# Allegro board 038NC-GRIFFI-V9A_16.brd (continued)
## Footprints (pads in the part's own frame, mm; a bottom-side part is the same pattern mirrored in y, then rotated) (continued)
PG_LTXDX_F_X1_PG400ND_SL12_V3
  round 0.051 hole 2.489x2.21 unplated: (36.185,-220.342)
  round 0.508 hole 3.2 unplated: (37.185,-154.842)
  rect 1.016x1.016 smd: A1(41.814,-218.796)
  round 1.016 smd: A2(42.939,-217.796) A3(41.814,-216.796) A4(42.939,-215.796) B1(39.565,-218.796) B2(40.69,-217.796) B3(39.565,-216.796) B4(40.69,-215.796) B62(40.69,-157.796) C1(37.314,-218.796) C2(38.44,-217.796) C3(37.314,-216.796) C4(38.44,-215.796) C62(38.44,-157.796) D1(35.064,-218.796) D2(36.189,-217.796) D3(35.064,-216.796) D4(36.189,-215.796) E1(32.815,-218.796) E2(33.939,-217.796) E3(32.815,-216.796) E4(33.939,-215.796) E62(33.939,-157.796) F1(30.565,-218.796) F2(31.69,-217.796) F3(30.565,-216.796) F4(31.69,-215.796) F62(31.69,-157.796) G2(29.44,-217.796) G4(29.44,-215.796) G6(29.44,-213.796) G8(29.44,-211.796) G10(29.44,-209.796) G12(29.44,-207.796) G14(29.44,-205.796) G16(29.44,-203.796) G18(29.44,-201.796) G20(29.44,-199.796) G22(29.44,-197.796) G24(29.44,-195.796) G26(29.44,-193.796) G28(29.44,-191.796) G30(29.44,-189.796) G32(29.44,-187.796) G34(29.44,-185.796) G36(29.44,-183.796) G38(29.44,-181.796) G40(29.44,-179.796) G42(29.44,-177.796) G44(29.44,-175.796) G46(29.44,-173.796) G48(29.44,-171.796) G50(29.44,-169.796) G52(29.44,-167.796) G54(29.44,-165.796) G56(29.44,-163.796) G58(29.44,-161.796) G60(29.44,-159.796)
  custom 0.257x0.257 smd: A5(41.814,-214.796) A6(42.939,-213.796) A7(41.814,-212.796) A8(42.939,-211.796) A9(41.814,-210.796) A10(42.939,-209.796) A11(41.814,-208.796) A12(42.939,-207.796) A13(41.814,-206.796) A14(42.939,-205.796) A15(41.814,-204.796) A16(42.939,-203.796) A17(41.814,-202.796) A18(42.939,-201.796) A19(41.814,-200.796) A20(42.939,-199.796) A21(41.814,-198.796) A22(42.939,-197.796) A23(41.814,-196.796) A24(42.939,-195.796) A25(41.814,-194.796) A26(42.939,-193.796) A27(41.814,-192.796) A28(42.939,-191.796) A29(41.814,-190.796) A30(42.939,-189.796) A31(41.814,-188.796) A32(42.939,-187.796) A33(41.814,-186.796) A34(42.939,-185.796) A35(41.814,-184.796) A36(42.939,-183.796) A37(41.814,-182.796) A38(42.939,-181.796) A39(41.814,-180.796) A40(42.939,-179.796) A41(41.814,-178.796) A42(42.939,-177.796) A43(41.814,-176.796) A44(42.939,-175.796) A45(41.814,-174.796) A46(42.939,-173.796) A47(41.814,-172.796) A48(42.939,-171.796) A49(41.814,-170.796) A50(42.939,-169.796) A51(41.814,-168.796) A52(42.939,-167.796) A53(41.814,-166.796) A54(42.939,-165.796) A55(41.814,-164.796) A56(42.939,-163.796) A57(41.814,-162.796) A58(42.939,-161.796) A59(41.814,-160.796) A60(42.939,-159.796) A61(41.814,-158.796) B5(39.565,-214.796) B6(40.69,-213.796) B7(39.565,-212.796) B8(40.69,-211.796) B9(39.565,-210.796) B10(40.69,-209.796) B11(39.565,-208.796) B12(40.69,-207.796) B13(39.565,-206.796) B14(40.69,-205.796) B15(39.565,-204.796) B16(40.69,-203.796) B17(39.565,-202.796) B18(40.69,-201.796) B19(39.565,-200.796) B20(40.69,-199.796) B21(39.565,-198.796) B22(40.69,-197.796) B23(39.565,-196.796) B24(40.69,-195.796) B25(39.565,-194.796) B26(40.69,-193.796) B27(39.565,-192.796) B28(40.69,-191.796) B29(39.565,-190.796) B30(40.69,-189.796) B31(39.565,-188.796) B32(40.69,-187.796) B33(39.565,-186.796) B34(40.69,-185.796) B35(39.565,-184.796) B36(40.69,-183.796) B37(39.565,-182.796) B38(40.69,-181.796) B39(39.565,-180.796) B40(40.69,-179.796) B41(39.565,-178.796) B42(40.69,-177.796) B43(39.565,-176.796) B44(40.69,-175.796) B45(39.565,-174.796) B46(40.69,-173.796) B47(39.565,-172.796) B48(40.69,-171.796) B49(39.565,-170.796) B50(40.69,-169.796) B51(39.565,-168.796) B52(40.69,-167.796) B53(39.565,-166.796) B54(40.69,-165.796) B55(39.565,-164.796) B56(40.69,-163.796) B57(39.565,-162.796) B58(40.69,-161.796) B59(39.565,-160.796) B60(40.69,-159.796) B61(39.565,-158.796) C5(37.314,-214.796) C6(38.44,-213.796) C7(37.314,-212.796) C8(38.44,-211.796) C9(37.314,-210.796) C10(38.44,-209.796) C11(37.314,-208.796) C12(38.44,-207.796) C13(37.314,-206.796) C14(38.44,-205.796) C15(37.314,-204.796) C16(38.44,-203.796) C17(37.314,-202.796) C18(38.44,-201.796) C19(37.314,-200.796) C20(38.44,-199.796) C21(37.314,-198.796) C22(38.44,-197.796) C23(37.314,-196.796) C24(38.44,-195.796) C25(37.314,-194.796) C26(38.44,-193.796) C27(37.314,-192.796) C28(38.44,-191.796) C29(37.314,-190.796) C30(38.44,-189.796) C31(37.314,-188.796) C32(38.44,-187.796) C33(37.314,-186.796) C34(38.44,-185.796) C35(37.314,-184.796) C36(38.44,-183.796) C37(37.314,-182.796) C38(38.44,-181.796) C39(37.314,-180.796) C40(38.44,-179.796) C41(37.314,-178.796) C42(38.44,-177.796) C43(37.314,-176.796) C44(38.44,-175.796) C45(37.314,-174.796) C46(38.44,-173.796) C47(37.314,-172.796) C48(38.44,-171.796) C49(37.314,-170.796) C50(38.44,-169.796) C51(37.314,-168.796) C52(38.44,-167.796) C53(37.314,-166.796) C54(38.44,-165.796) C55(37.314,-164.796) C56(38.44,-163.796) C57(37.314,-162.796) C58(38.44,-161.796) C59(37.314,-160.796) C60(38.44,-159.796) C61(37.314,-158.796) D5(35.064,-214.796) D6(36.189,-213.796) D7(35.064,-212.796) D8(36.189,-211.796) D9(35.064,-210.796) D10(36.189,-209.796) D11(35.064,-208.796) D12(36.189,-207.796) D13(35.064,-206.796) D14(36.189,-205.796) D15(35.064,-204.796) D16(36.189,-203.796) D17(35.064,-202.796) D18(36.189,-201.796) D19(35.064,-200.796) D20(36.189,-199.796) D21(35.064,-198.796) D22(36.189,-197.796) D23(35.064,-196.796) D24(36.189,-195.796) D25(35.064,-194.796) D26(36.189,-193.796) D27(35.064,-192.796) D28(36.189,-191.796) D29(35.064,-190.796) D30(36.189,-189.796) D31(35.064,-188.796) D32(36.189,-187.796) D33(35.064,-186.796) D34(36.189,-185.796) D35(35.064,-184.796) D36(36.189,-183.796) D37(35.064,-182.796) D38(36.189,-181.796) D39(35.064,-180.796) D40(36.189,-179.796) D41(35.064,-178.796) D42(36.189,-177.796) D43(35.064,-176.796) D44(36.189,-175.796) D45(35.064,-174.796) D46(36.189,-173.796) D47(35.064,-172.796) D48(36.189,-171.796) D49(35.064,-170.796) D50(36.189,-169.796) D51(35.064,-168.796) D52(36.189,-167.796) D53(35.064,-166.796) D54(36.189,-165.796) D55(35.064,-164.796) D56(36.189,-163.796) D57(35.064,-162.796) D58(36.189,-161.796) D59(35.064,-160.796) D60(36.189,-159.796) D61(35.064,-158.796) E5(32.815,-214.796) E6(33.939,-213.796) E7(32.815,-212.796) E8(33.939,-211.796) E9(32.815,-210.796) E10(33.939,-209.796) E11(32.815,-208.796) E12(33.939,-207.796) E13(32.815,-206.796) E14(33.939,-205.796) E15(32.815,-204.796) E16(33.939,-203.796) E17(32.815,-202.796) E18(33.939,-201.796) E19(32.815,-200.796) E20(33.939,-199.796) E21(32.815,-198.796) E22(33.939,-197.796) E23(32.815,-196.796) E24(33.939,-195.796) E25(32.815,-194.796) E26(33.939,-193.796) E27(32.815,-192.796) E28(33.939,-191.796) E29(32.815,-190.796) E30(33.939,-189.796) E31(32.815,-188.796) E32(33.939,-187.796) E33(32.815,-186.796) E34(33.939,-185.796) E35(32.815,-184.796) E36(33.939,-183.796) E37(32.815,-182.796) E38(33.939,-181.796) E39(32.815,-180.796) E40(33.939,-179.796) E41(32.815,-178.796) E42(33.939,-177.796) E43(32.815,-176.796) E44(33.939,-175.796) E45(32.815,-174.796) E46(33.939,-173.796) E47(32.815,-172.796) E48(33.939,-171.796) E49(32.815,-170.796) E50(33.939,-169.796) E51(32.815,-168.796) E52(33.939,-167.796) E53(32.815,-166.796) E54(33.939,-165.796) E55(32.815,-164.796) E56(33.939,-163.796) E57(32.815,-162.796) E58(33.939,-161.796) E59(32.815,-160.796) E60(33.939,-159.796) E61(32.815,-158.796) F5(30.565,-214.796) F6(31.69,-213.796) F7(30.565,-212.796) F8(31.69,-211.796) F9(30.565,-210.796) F10(31.69,-209.796) F11(30.565,-208.796) F12(31.69,-207.796) F13(30.565,-206.796) F14(31.69,-205.796) F15(30.565,-204.796) F16(31.69,-203.796) F17(30.565,-202.796) F18(31.69,-201.796) F19(30.565,-200.796) F20(31.69,-199.796) F21(30.565,-198.796) F22(31.69,-197.796) F23(30.565,-196.796) F24(31.69,-195.796) F25(30.565,-194.796) F26(31.69,-193.796) F27(30.565,-192.796) F28(31.69,-191.796) F29(30.565,-190.796) F30(31.69,-189.796) F31(30.565,-188.796) F32(31.69,-187.796) F33(30.565,-186.796) F34(31.69,-185.796) F35(30.565,-184.796) F36(31.69,-183.796) F37(30.565,-182.796) F38(31.69,-181.796) F39(30.565,-180.796) F40(31.69,-179.796) F41(30.565,-178.796) F42(31.69,-177.796) F43(30.565,-176.796) F44(31.69,-175.796) F45(30.565,-174.796) F46(31.69,-173.796) F47(30.565,-172.796) F48(31.69,-171.796) F49(30.565,-170.796) F50(31.69,-169.796) F51(30.565,-168.796) F52(31.69,-167.796) F53(30.565,-166.796) F54(31.69,-165.796) F55(30.565,-164.796) F56(31.69,-163.796) F57(30.565,-162.796) F58(31.69,-161.796) F59(30.565,-160.796) F60(31.69,-159.796) F61(30.565,-158.796) Z5(44.064,-214.796) Z7(44.064,-212.796) Z9(44.064,-210.796) Z11(44.064,-208.796) Z13(44.064,-206.796) Z15(44.064,-204.796) Z17(44.064,-202.796) Z19(44.064,-200.796) Z21(44.064,-198.796) Z23(44.064,-196.796) Z25(44.064,-194.796) Z27(44.064,-192.796) Z29(44.064,-190.796) Z31(44.064,-188.796) Z33(44.064,-186.796) Z35(44.064,-184.796) Z37(44.064,-182.796) Z39(44.064,-180.796) Z41(44.064,-178.796) Z43(44.064,-176.796) Z45(44.064,-174.796) Z47(44.064,-172.796) Z49(44.064,-170.796) Z51(44.064,-168.796) Z53(44.064,-166.796) Z55(44.064,-164.796) Z57(44.064,-162.796) Z59(44.064,-160.796) Z61(44.064,-158.796)
PG_LTXDX_F_X1_PG400ND_SL14_V3
  round 0.051 hole 2.489x2.21 unplated: (60.315,-220.342)
  round 0.508 hole 3.2 unplated: (61.315,-154.842)
  rect 1.016x1.016 smd: A1(65.944,-218.796)
  round 1.016 smd: A2(67.069,-217.796) A3(65.944,-216.796) A4(67.069,-215.796) B1(63.695,-218.796) B2(64.82,-217.796) B3(63.695,-216.796) B4(64.82,-215.796) B62(64.82,-157.796) C1(61.444,-218.796) C2(62.57,-217.796) C3(61.444,-216.796) C4(62.57,-215.796) C62(62.57,-157.796) D1(59.194,-218.796) D2(60.319,-217.796) D3(59.194,-216.796) D4(60.319,-215.796) E1(56.945,-218.796) E2(58.069,-217.796) E3(56.945,-216.796) E4(58.069,-215.796) E62(58.069,-157.796) F1(54.695,-218.796) F2(55.82,-217.796) F3(54.695,-216.796) F4(55.82,-215.796) F62(55.82,-157.796) G2(53.57,-217.796) G4(53.57,-215.796) G6(53.57,-213.796) G8(53.57,-211.796) G10(53.57,-209.796) G12(53.57,-207.796) G14(53.57,-205.796) G16(53.57,-203.796) G18(53.57,-201.796) G20(53.57,-199.796) G22(53.57,-197.796) G24(53.57,-195.796) G26(53.57,-193.796) G28(53.57,-191.796) G30(53.57,-189.796) G32(53.57,-187.796) G34(53.57,-185.796) G36(53.57,-183.796) G38(53.57,-181.796) G40(53.57,-179.796) G42(53.57,-177.796) G44(53.57,-175.796) G46(53.57,-173.796) G48(53.57,-171.796) G50(53.57,-169.796) G52(53.57,-167.796) G54(53.57,-165.796) G56(53.57,-163.796) G58(53.57,-161.796) G60(53.57,-159.796)
  custom 0.257x0.257 smd: A5(65.944,-214.796) A6(67.069,-213.796) A7(65.944,-212.796) A8(67.069,-211.796) A9(65.944,-210.796) A10(67.069,-209.796) A11(65.944,-208.796) A12(67.069,-207.796) A13(65.944,-206.796) A14(67.069,-205.796) A15(65.944,-204.796) A16(67.069,-203.796) A17(65.944,-202.796) A18(67.069,-201.796) A19(65.944,-200.796) A20(67.069,-199.796) A21(65.944,-198.796) A22(67.069,-197.796) A23(65.944,-196.796) A24(67.069,-195.796) A25(65.944,-194.796) A26(67.069,-193.796) A27(65.944,-192.796) A28(67.069,-191.796) A29(65.944,-190.796) A30(67.069,-189.796) A31(65.944,-188.796) A32(67.069,-187.796) A33(65.944,-186.796) A34(67.069,-185.796) A35(65.944,-184.796) A36(67.069,-183.796) A37(65.944,-182.796) A38(67.069,-181.796) A39(65.944,-180.796) A40(67.069,-179.796) A41(65.944,-178.796) A42(67.069,-177.796) A43(65.944,-176.796) A44(67.069,-175.796) A45(65.944,-174.796) A46(67.069,-173.796) A47(65.944,-172.796) A48(67.069,-171.796) A49(65.944,-170.796) A50(67.069,-169.796) A51(65.944,-168.796) A52(67.069,-167.796) A53(65.944,-166.796) A54(67.069,-165.796) A55(65.944,-164.796) A56(67.069,-163.796) A57(65.944,-162.796) A58(67.069,-161.796) A59(65.944,-160.796) A60(67.069,-159.796) A61(65.944,-158.796) B5(63.695,-214.796) B6(64.82,-213.796) B7(63.695,-212.796) B8(64.82,-211.796) B9(63.695,-210.796) B10(64.82,-209.796) B11(63.695,-208.796) B12(64.82,-207.796) B13(63.695,-206.796) B14(64.82,-205.796) B15(63.695,-204.796) B16(64.82,-203.796) B17(63.695,-202.796) B18(64.82,-201.796) B19(63.695,-200.796) B20(64.82,-199.796) B21(63.695,-198.796) B22(64.82,-197.796) B23(63.695,-196.796) B24(64.82,-195.796) B25(63.695,-194.796) B26(64.82,-193.796) B27(63.695,-192.796) B28(64.82,-191.796) B29(63.695,-190.796) B30(64.82,-189.796) B31(63.695,-188.796) B32(64.82,-187.796) B33(63.695,-186.796) B34(64.82,-185.796) B35(63.695,-184.796) B36(64.82,-183.796) B37(63.695,-182.796) B38(64.82,-181.796) B39(63.695,-180.796) B40(64.82,-179.796) B41(63.695,-178.796) B42(64.82,-177.796) B43(63.695,-176.796) B44(64.82,-175.796) B45(63.695,-174.796) B46(64.82,-173.796) B47(63.695,-172.796) B48(64.82,-171.796) B49(63.695,-170.796) B50(64.82,-169.796) B51(63.695,-168.796) B52(64.82,-167.796) B53(63.695,-166.796) B54(64.82,-165.796) B55(63.695,-164.796) B56(64.82,-163.796) B57(63.695,-162.796) B58(64.82,-161.796) B59(63.695,-160.796) B60(64.82,-159.796) B61(63.695,-158.796) C5(61.444,-214.796) C6(62.57,-213.796) C7(61.444,-212.796) C8(62.57,-211.796) C9(61.444,-210.796) C10(62.57,-209.796) C11(61.444,-208.796) C12(62.57,-207.796) C13(61.444,-206.796) C14(62.57,-205.796) C15(61.444,-204.796) C16(62.57,-203.796) C17(61.444,-202.796) C18(62.57,-201.796) C19(61.444,-200.796) C20(62.57,-199.796) C21(61.444,-198.796) C22(62.57,-197.796) C23(61.444,-196.796) C24(62.57,-195.796) C25(61.444,-194.796) C26(62.57,-193.796) C27(61.444,-192.796) C28(62.57,-191.796) C29(61.444,-190.796) C30(62.57,-189.796) C31(61.444,-188.796) C32(62.57,-187.796) C33(61.444,-186.796) C34(62.57,-185.796) C35(61.444,-184.796) C36(62.57,-183.796) C37(61.444,-182.796) C38(62.57,-181.796) C39(61.444,-180.796) C40(62.57,-179.796) C41(61.444,-178.796) C42(62.57,-177.796) C43(61.444,-176.796) C44(62.57,-175.796) C45(61.444,-174.796) C46(62.57,-173.796) C47(61.444,-172.796) C48(62.57,-171.796) C49(61.444,-170.796) C50(62.57,-169.796) C51(61.444,-168.796) C52(62.57,-167.796) C53(61.444,-166.796) C54(62.57,-165.796) C55(61.444,-164.796) C56(62.57,-163.796) C57(61.444,-162.796) C58(62.57,-161.796) C59(61.444,-160.796) C60(62.57,-159.796) C61(61.444,-158.796) D5(59.194,-214.796) D6(60.319,-213.796) D7(59.194,-212.796) D8(60.319,-211.796) D9(59.194,-210.796) D10(60.319,-209.796) D11(59.194,-208.796) D12(60.319,-207.796) D13(59.194,-206.796) D14(60.319,-205.796) D15(59.194,-204.796) D16(60.319,-203.796) D17(59.194,-202.796) D18(60.319,-201.796) D19(59.194,-200.796) D20(60.319,-199.796) D21(59.194,-198.796) D22(60.319,-197.796) D23(59.194,-196.796) D24(60.319,-195.796) D25(59.194,-194.796) D26(60.319,-193.796) D27(59.194,-192.796) D28(60.319,-191.796) D29(59.194,-190.796) D30(60.319,-189.796) D31(59.194,-188.796) D32(60.319,-187.796) D33(59.194,-186.796) D34(60.319,-185.796) D35(59.194,-184.796) D36(60.319,-183.796) D37(59.194,-182.796) D38(60.319,-181.796) D39(59.194,-180.796) D40(60.319,-179.796) D41(59.194,-178.796) D42(60.319,-177.796) D43(59.194,-176.796) D44(60.319,-175.796) D45(59.194,-174.796) D46(60.319,-173.796) D47(59.194,-172.796) D48(60.319,-171.796) D49(59.194,-170.796) D50(60.319,-169.796) D51(59.194,-168.796) D52(60.319,-167.796) D53(59.194,-166.796) D54(60.319,-165.796) D55(59.194,-164.796) D56(60.319,-163.796) D57(59.194,-162.796) D58(60.319,-161.796) D59(59.194,-160.796) D60(60.319,-159.796) D61(59.194,-158.796) E5(56.945,-214.796) E6(58.069,-213.796) E7(56.945,-212.796) E8(58.069,-211.796) E9(56.945,-210.796) E10(58.069,-209.796) E11(56.945,-208.796) E12(58.069,-207.796) E13(56.945,-206.796) E14(58.069,-205.796) E15(56.945,-204.796) E16(58.069,-203.796) E17(56.945,-202.796) E18(58.069,-201.796) E19(56.945,-200.796) E20(58.069,-199.796) E21(56.945,-198.796) E22(58.069,-197.796) E23(56.945,-196.796) E24(58.069,-195.796) E25(56.945,-194.796) E26(58.069,-193.796) E27(56.945,-192.796) E28(58.069,-191.796) E29(56.945,-190.796) E30(58.069,-189.796) E31(56.945,-188.796) E32(58.069,-187.796) E33(56.945,-186.796) E34(58.069,-185.796) E35(56.945,-184.796) E36(58.069,-183.796) E37(56.945,-182.796) E38(58.069,-181.796) E39(56.945,-180.796) E40(58.069,-179.796) E41(56.945,-178.796) E42(58.069,-177.796) E43(56.945,-176.796) E44(58.069,-175.796) E45(56.945,-174.796) E46(58.069,-173.796) E47(56.945,-172.796) E48(58.069,-171.796) E49(56.945,-170.796) E50(58.069,-169.796) E51(56.945,-168.796) E52(58.069,-167.796) E53(56.945,-166.796) E54(58.069,-165.796) E55(56.945,-164.796) E56(58.069,-163.796) E57(56.945,-162.796) E58(58.069,-161.796) E59(56.945,-160.796) E60(58.069,-159.796) E61(56.945,-158.796) F5(54.695,-214.796) F6(55.82,-213.796) F7(54.695,-212.796) F8(55.82,-211.796) F9(54.695,-210.796) F10(55.82,-209.796) F11(54.695,-208.796) F12(55.82,-207.796) F13(54.695,-206.796) F14(55.82,-205.796) F15(54.695,-204.796) F16(55.82,-203.796) F17(54.695,-202.796) F18(55.82,-201.796) F19(54.695,-200.796) F20(55.82,-199.796) F21(54.695,-198.796) F22(55.82,-197.796) F23(54.695,-196.796) F24(55.82,-195.796) F25(54.695,-194.796) F26(55.82,-193.796) F27(54.695,-192.796) F28(55.82,-191.796) F29(54.695,-190.796) F30(55.82,-189.796) F31(54.695,-188.796) F32(55.82,-187.796) F33(54.695,-186.796) F34(55.82,-185.796) F35(54.695,-184.796) F36(55.82,-183.796) F37(54.695,-182.796) F38(55.82,-181.796) F39(54.695,-180.796) F40(55.82,-179.796) F41(54.695,-178.796) F42(55.82,-177.796) F43(54.695,-176.796) F44(55.82,-175.796) F45(54.695,-174.796) F46(55.82,-173.796) F47(54.695,-172.796) F48(55.82,-171.796) F49(54.695,-170.796) F50(55.82,-169.796) F51(54.695,-168.796) F52(55.82,-167.796) F53(54.695,-166.796) F54(55.82,-165.796) F55(54.695,-164.796) F56(55.82,-163.796) F57(54.695,-162.796) F58(55.82,-161.796) F59(54.695,-160.796) F60(55.82,-159.796) F61(54.695,-158.796) Z5(68.194,-214.796) Z7(68.194,-212.796) Z9(68.194,-210.796) Z11(68.194,-208.796) Z13(68.194,-206.796) Z15(68.194,-204.796) Z17(68.194,-202.796) Z19(68.194,-200.796) Z21(68.194,-198.796) Z23(68.194,-196.796) Z25(68.194,-194.796) Z27(68.194,-192.796) Z29(68.194,-190.796) Z31(68.194,-188.796) Z33(68.194,-186.796) Z35(68.194,-184.796) Z37(68.194,-182.796) Z39(68.194,-180.796) Z41(68.194,-178.796) Z43(68.194,-176.796) Z45(68.194,-174.796) Z47(68.194,-172.796) Z49(68.194,-170.796) Z51(68.194,-168.796) Z53(68.194,-166.796) Z55(68.194,-164.796) Z57(68.194,-162.796) Z59(68.194,-160.796) Z61(68.194,-158.796)
PG_LTXDX_F_X1_PG400ND_SL15_V3
  round 0.508 hole 3.2 unplated: (59.335,154.842)
  round 0.051 hole 2.489x2.21 unplated: (60.335,220.342)
  rect 1.016x1.016 smd: A1(54.706,218.796)
  round 1.016 smd: A2(53.581,217.796) A3(54.706,216.796) A4(53.581,215.796) B1(56.955,218.796) B2(55.83,217.796) B3(56.955,216.796) B4(55.83,215.796) B62(55.83,157.796) C1(59.206,218.796) C2(58.08,217.796) C3(59.206,216.796) C4(58.08,215.796) C62(58.08,157.796) D1(61.456,218.796) D2(60.331,217.796) D3(61.456,216.796) D4(60.331,215.796) E1(63.705,218.796) E2(62.581,217.796) E3(63.705,216.796) E4(62.581,215.796) E62(62.581,157.796) F1(65.955,218.796) F2(64.83,217.796) F3(65.955,216.796) F4(64.83,215.796) F62(64.83,157.796) G2(67.08,217.796) G4(67.08,215.796) G6(67.08,213.796) G8(67.08,211.796) G10(67.08,209.796) G12(67.08,207.796) G14(67.08,205.796) G16(67.08,203.796) G18(67.08,201.796) G20(67.08,199.796) G22(67.08,197.796) G24(67.08,195.796) G26(67.08,193.796) G28(67.08,191.796) G30(67.08,189.796) G32(67.08,187.796) G34(67.08,185.796) G36(67.08,183.796) G38(67.08,181.796) G40(67.08,179.796) G42(67.08,177.796) G44(67.08,175.796) G46(67.08,173.796) G48(67.08,171.796) G50(67.08,169.796) G52(67.08,167.796) G54(67.08,165.796) G56(67.08,163.796) G58(67.08,161.796) G60(67.08,159.796)
  custom 0.257x0.257 smd: A5(54.706,214.796) A6(53.581,213.796) A7(54.706,212.796) A8(53.581,211.796) A9(54.706,210.796) A10(53.581,209.796) A11(54.706,208.796) A12(53.581,207.796) A13(54.706,206.796) A14(53.581,205.796) A15(54.706,204.796) A16(53.581,203.796) A17(54.706,202.796) A18(53.581,201.796) A19(54.706,200.796) A20(53.581,199.796) A21(54.706,198.796) A22(53.581,197.796) A23(54.706,196.796) A24(53.581,195.796) A25(54.706,194.796) A26(53.581,193.796) A27(54.706,192.796) A28(53.581,191.796) A29(54.706,190.796) A30(53.581,189.796) A31(54.706,188.796) A32(53.581,187.796) A33(54.706,186.796) A34(53.581,185.796) A35(54.706,184.796) A36(53.581,183.796) A37(54.706,182.796) A38(53.581,181.796) A39(54.706,180.796) A40(53.581,179.796) A41(54.706,178.796) A42(53.581,177.796) A43(54.706,176.796) A44(53.581,175.796) A45(54.706,174.796) A46(53.581,173.796) A47(54.706,172.796) A48(53.581,171.796) A49(54.706,170.796) A50(53.581,169.796) A51(54.706,168.796) A52(53.581,167.796) A53(54.706,166.796) A54(53.581,165.796) A55(54.706,164.796) A56(53.581,163.796) A57(54.706,162.796) A58(53.581,161.796) A59(54.706,160.796) A60(53.581,159.796) A61(54.706,158.796) B5(56.955,214.796) B6(55.83,213.796) B7(56.955,212.796) B8(55.83,211.796) B9(56.955,210.796) B10(55.83,209.796) B11(56.955,208.796) B12(55.83,207.796) B13(56.955,206.796) B14(55.83,205.796) B15(56.955,204.796) B16(55.83,203.796) B17(56.955,202.796) B18(55.83,201.796) B19(56.955,200.796) B20(55.83,199.796) B21(56.955,198.796) B22(55.83,197.796) B23(56.955,196.796) B24(55.83,195.796) B25(56.955,194.796) B26(55.83,193.796) B27(56.955,192.796) B28(55.83,191.796) B29(56.955,190.796) B30(55.83,189.796) B31(56.955,188.796) B32(55.83,187.796) B33(56.955,186.796) B34(55.83,185.796) B35(56.955,184.796) B36(55.83,183.796) B37(56.955,182.796) B38(55.83,181.796) B39(56.955,180.796) B40(55.83,179.796) B41(56.955,178.796) B42(55.83,177.796) B43(56.955,176.796) B44(55.83,175.796) B45(56.955,174.796) B46(55.83,173.796) B47(56.955,172.796) B48(55.83,171.796) B49(56.955,170.796) B50(55.83,169.796) B51(56.955,168.796) B52(55.83,167.796) B53(56.955,166.796) B54(55.83,165.796) B55(56.955,164.796) B56(55.83,163.796) B57(56.955,162.796) B58(55.83,161.796) B59(56.955,160.796) B60(55.83,159.796) B61(56.955,158.796) C5(59.206,214.796) C6(58.08,213.796) C7(59.206,212.796) C8(58.08,211.796) C9(59.206,210.796) C10(58.08,209.796) C11(59.206,208.796) C12(58.08,207.796) C13(59.206,206.796) C14(58.08,205.796) C15(59.206,204.796) C16(58.08,203.796) C17(59.206,202.796) C18(58.08,201.796) C19(59.206,200.796) C20(58.08,199.796) C21(59.206,198.796) C22(58.08,197.796) C23(59.206,196.796) C24(58.08,195.796) C25(59.206,194.796) C26(58.08,193.796) C27(59.206,192.796) C28(58.08,191.796) C29(59.206,190.796) C30(58.08,189.796) C31(59.206,188.796) C32(58.08,187.796) C33(59.206,186.796) C34(58.08,185.796) C35(59.206,184.796) C36(58.08,183.796) C37(59.206,182.796) C38(58.08,181.796) C39(59.206,180.796) C40(58.08,179.796) C41(59.206,178.796) C42(58.08,177.796) C43(59.206,176.796) C44(58.08,175.796) C45(59.206,174.796) C46(58.08,173.796) C47(59.206,172.796) C48(58.08,171.796) C49(59.206,170.796) C50(58.08,169.796) C51(59.206,168.796) C52(58.08,167.796) C53(59.206,166.796) C54(58.08,165.796) C55(59.206,164.796) C56(58.08,163.796) C57(59.206,162.796) C58(58.08,161.796) C59(59.206,160.796) C60(58.08,159.796) C61(59.206,158.796) D5(61.456,214.796) D6(60.331,213.796) D7(61.456,212.796) D8(60.331,211.796) D9(61.456,210.796) D10(60.331,209.796) D11(61.456,208.796) D12(60.331,207.796) D13(61.456,206.796) D14(60.331,205.796) D15(61.456,204.796) D16(60.331,203.796) D17(61.456,202.796) D18(60.331,201.796) D19(61.456,200.796) D20(60.331,199.796) D21(61.456,198.796) D22(60.331,197.796) D23(61.456,196.796) D24(60.331,195.796) D25(61.456,194.796) D26(60.331,193.796) D27(61.456,192.796) D28(60.331,191.796) D29(61.456,190.796) D30(60.331,189.796) D31(61.456,188.796) D32(60.331,187.796) D33(61.456,186.796) D34(60.331,185.796) D35(61.456,184.796) D36(60.331,183.796) D37(61.456,182.796) D38(60.331,181.796) D39(61.456,180.796) D40(60.331,179.796) D41(61.456,178.796) D42(60.331,177.796) D43(61.456,176.796) D44(60.331,175.796) D45(61.456,174.796) D46(60.331,173.796) D47(61.456,172.796) D48(60.331,171.796) D49(61.456,170.796) D50(60.331,169.796) D51(61.456,168.796) D52(60.331,167.796) D53(61.456,166.796) D54(60.331,165.796) D55(61.456,164.796) D56(60.331,163.796) D57(61.456,162.796) D58(60.331,161.796) D59(61.456,160.796) D60(60.331,159.796) D61(61.456,158.796) E5(63.705,214.796) E6(62.581,213.796) E7(63.705,212.796) E8(62.581,211.796) E9(63.705,210.796) E10(62.581,209.796) E11(63.705,208.796) E12(62.581,207.796) E13(63.705,206.796) E14(62.581,205.796) E15(63.705,204.796) E16(62.581,203.796) E17(63.705,202.796) E18(62.581,201.796) E19(63.705,200.796) E20(62.581,199.796) E21(63.705,198.796) E22(62.581,197.796) E23(63.705,196.796) E24(62.581,195.796) E25(63.705,194.796) E26(62.581,193.796) E27(63.705,192.796) E28(62.581,191.796) E29(63.705,190.796) E30(62.581,189.796) E31(63.705,188.796) E32(62.581,187.796) E33(63.705,186.796) E34(62.581,185.796) E35(63.705,184.796) E36(62.581,183.796) E37(63.705,182.796) E38(62.581,181.796) E39(63.705,180.796) E40(62.581,179.796) E41(63.705,178.796) E42(62.581,177.796) E43(63.705,176.796) E44(62.581,175.796) E45(63.705,174.796) E46(62.581,173.796) E47(63.705,172.796) E48(62.581,171.796) E49(63.705,170.796) E50(62.581,169.796) E51(63.705,168.796) E52(62.581,167.796) E53(63.705,166.796) E54(62.581,165.796) E55(63.705,164.796) E56(62.581,163.796) E57(63.705,162.796) E58(62.581,161.796) E59(63.705,160.796) E60(62.581,159.796) E61(63.705,158.796) F5(65.955,214.796) F6(64.83,213.796) F7(65.955,212.796) F8(64.83,211.796) F9(65.955,210.796) F10(64.83,209.796) F11(65.955,208.796) F12(64.83,207.796) F13(65.955,206.796) F14(64.83,205.796) F15(65.955,204.796) F16(64.83,203.796) F17(65.955,202.796) F18(64.83,201.796) F19(65.955,200.796) F20(64.83,199.796) F21(65.955,198.796) F22(64.83,197.796) F23(65.955,196.796) F24(64.83,195.796) F25(65.955,194.796) F26(64.83,193.796) F27(65.955,192.796) F28(64.83,191.796) F29(65.955,190.796) F30(64.83,189.796) F31(65.955,188.796) F32(64.83,187.796) F33(65.955,186.796) F34(64.83,185.796) F35(65.955,184.796) F36(64.83,183.796) F37(65.955,182.796) F38(64.83,181.796) F39(65.955,180.796) F40(64.83,179.796) F41(65.955,178.796) F42(64.83,177.796) F43(65.955,176.796) F44(64.83,175.796) F45(65.955,174.796) F46(64.83,173.796) F47(65.955,172.796) F48(64.83,171.796) F49(65.955,170.796) F50(64.83,169.796) F51(65.955,168.796) F52(64.83,167.796) F53(65.955,166.796) F54(64.83,165.796) F55(65.955,164.796) F56(64.83,163.796) F57(65.955,162.796) F58(64.83,161.796) F59(65.955,160.796) F60(64.83,159.796) F61(65.955,158.796) Z5(52.456,214.796) Z7(52.456,212.796) Z9(52.456,210.796) Z11(52.456,208.796) Z13(52.456,206.796) Z15(52.456,204.796) Z17(52.456,202.796) Z19(52.456,200.796) Z21(52.456,198.796) Z23(52.456,196.796) Z25(52.456,194.796) Z27(52.456,192.796) Z29(52.456,190.796) Z31(52.456,188.796) Z33(52.456,186.796) Z35(52.456,184.796) Z37(52.456,182.796) Z39(52.456,180.796) Z41(52.456,178.796) Z43(52.456,176.796) Z45(52.456,174.796) Z47(52.456,172.796) Z49(52.456,170.796) Z51(52.456,168.796) Z53(52.456,166.796) Z55(52.456,164.796) Z57(52.456,162.796) Z59(52.456,160.796) Z61(52.456,158.796)
PG_LTXDX_F_X1_PG400ND_SL16_V3
  round 0.051 hole 2.489x2.21 unplated: (84.445,-220.342)
  round 0.508 hole 3.2 unplated: (85.445,-154.842)
  rect 1.016x1.016 smd: A1(90.074,-218.796)
  round 1.016 smd: A2(91.199,-217.796) A3(90.074,-216.796) A4(91.199,-215.796) B1(87.825,-218.796) B2(88.95,-217.796) B3(87.825,-216.796) B4(88.95,-215.796) B62(88.95,-157.796) C1(85.574,-218.796) C2(86.7,-217.796) C3(85.574,-216.796) C4(86.7,-215.796) C62(86.7,-157.796) D1(83.324,-218.796) D2(84.449,-217.796) D3(83.324,-216.796) D4(84.449,-215.796) E1(81.075,-218.796) E2(82.199,-217.796) E3(81.075,-216.796) E4(82.199,-215.796) E62(82.199,-157.796) F1(78.825,-218.796) F2(79.95,-217.796) F3(78.825,-216.796) F4(79.95,-215.796) F62(79.95,-157.796) G2(77.7,-217.796) G4(77.7,-215.796) G6(77.7,-213.796) G8(77.7,-211.796) G10(77.7,-209.796) G12(77.7,-207.796) G14(77.7,-205.796) G16(77.7,-203.796) G18(77.7,-201.796) G20(77.7,-199.796) G22(77.7,-197.796) G24(77.7,-195.796) G26(77.7,-193.796) G28(77.7,-191.796) G30(77.7,-189.796) G32(77.7,-187.796) G34(77.7,-185.796) G36(77.7,-183.796) G38(77.7,-181.796) G40(77.7,-179.796) G42(77.7,-177.796) G44(77.7,-175.796) G46(77.7,-173.796) G48(77.7,-171.796) G50(77.7,-169.796) G52(77.7,-167.796) G54(77.7,-165.796) G56(77.7,-163.796) G58(77.7,-161.796) G60(77.7,-159.796)
  custom 0.257x0.257 smd: A5(90.074,-214.796) A6(91.199,-213.796) A7(90.074,-212.796) A8(91.199,-211.796) A9(90.074,-210.796) A10(91.199,-209.796) A11(90.074,-208.796) A12(91.199,-207.796) A13(90.074,-206.796) A14(91.199,-205.796) A15(90.074,-204.796) A16(91.199,-203.796) A17(90.074,-202.796) A18(91.199,-201.796) A19(90.074,-200.796) A20(91.199,-199.796) A21(90.074,-198.796) A22(91.199,-197.796) A23(90.074,-196.796) A24(91.199,-195.796) A25(90.074,-194.796) A26(91.199,-193.796) A27(90.074,-192.796) A28(91.199,-191.796) A29(90.074,-190.796) A30(91.199,-189.796) A31(90.074,-188.796) A32(91.199,-187.796) A33(90.074,-186.796) A34(91.199,-185.796) A35(90.074,-184.796) A36(91.199,-183.796) A37(90.074,-182.796) A38(91.199,-181.796) A39(90.074,-180.796) A40(91.199,-179.796) A41(90.074,-178.796) A42(91.199,-177.796) A43(90.074,-176.796) A44(91.199,-175.796) A45(90.074,-174.796) A46(91.199,-173.796) A47(90.074,-172.796) A48(91.199,-171.796) A49(90.074,-170.796) A50(91.199,-169.796) A51(90.074,-168.796) A52(91.199,-167.796) A53(90.074,-166.796) A54(91.199,-165.796) A55(90.074,-164.796) A56(91.199,-163.796) A57(90.074,-162.796) A58(91.199,-161.796) A59(90.074,-160.796) A60(91.199,-159.796) A61(90.074,-158.796) B5(87.825,-214.796) B6(88.95,-213.796) B7(87.825,-212.796) B8(88.95,-211.796) B9(87.825,-210.796) B10(88.95,-209.796) B11(87.825,-208.796) B12(88.95,-207.796) B13(87.825,-206.796) B14(88.95,-205.796) B15(87.825,-204.796) B16(88.95,-203.796) B17(87.825,-202.796) B18(88.95,-201.796) B19(87.825,-200.796) B20(88.95,-199.796) B21(87.825,-198.796) B22(88.95,-197.796) B23(87.825,-196.796) B24(88.95,-195.796) B25(87.825,-194.796) B26(88.95,-193.796) B27(87.825,-192.796) B28(88.95,-191.796) B29(87.825,-190.796) B30(88.95,-189.796) B31(87.825,-188.796) B32(88.95,-187.796) B33(87.825,-186.796) B34(88.95,-185.796) B35(87.825,-184.796) B36(88.95,-183.796) B37(87.825,-182.796) B38(88.95,-181.796) B39(87.825,-180.796) B40(88.95,-179.796) B41(87.825,-178.796) B42(88.95,-177.796) B43(87.825,-176.796) B44(88.95,-175.796) B45(87.825,-174.796) B46(88.95,-173.796) B47(87.825,-172.796) B48(88.95,-171.796) B49(87.825,-170.796) B50(88.95,-169.796) B51(87.825,-168.796) B52(88.95,-167.796) B53(87.825,-166.796) B54(88.95,-165.796) B55(87.825,-164.796) B56(88.95,-163.796) B57(87.825,-162.796) B58(88.95,-161.796) B59(87.825,-160.796) B60(88.95,-159.796) B61(87.825,-158.796) C5(85.574,-214.796) C6(86.7,-213.796) C7(85.574,-212.796) C8(86.7,-211.796) C9(85.574,-210.796) C10(86.7,-209.796) C11(85.574,-208.796) C12(86.7,-207.796) C13(85.574,-206.796) C14(86.7,-205.796) C15(85.574,-204.796) C16(86.7,-203.796) C17(85.574,-202.796) C18(86.7,-201.796) C19(85.574,-200.796) C20(86.7,-199.796) C21(85.574,-198.796) C22(86.7,-197.796) C23(85.574,-196.796) C24(86.7,-195.796) C25(85.574,-194.796) C26(86.7,-193.796) C27(85.574,-192.796) C28(86.7,-191.796) C29(85.574,-190.796) C30(86.7,-189.796) C31(85.574,-188.796) C32(86.7,-187.796) C33(85.574,-186.796) C34(86.7,-185.796) C35(85.574,-184.796) C36(86.7,-183.796) C37(85.574,-182.796) C38(86.7,-181.796) C39(85.574,-180.796) C40(86.7,-179.796) C41(85.574,-178.796) C42(86.7,-177.796) C43(85.574,-176.796) C44(86.7,-175.796) C45(85.574,-174.796) C46(86.7,-173.796) C47(85.574,-172.796) C48(86.7,-171.796) C49(85.574,-170.796) C50(86.7,-169.796) C51(85.574,-168.796) C52(86.7,-167.796) C53(85.574,-166.796) C54(86.7,-165.796) C55(85.574,-164.796) C56(86.7,-163.796) C57(85.574,-162.796) C58(86.7,-161.796) C59(85.574,-160.796) C60(86.7,-159.796) C61(85.574,-158.796) D5(83.324,-214.796) D6(84.449,-213.796) D7(83.324,-212.796) D8(84.449,-211.796) D9(83.324,-210.796) D10(84.449,-209.796) D11(83.324,-208.796) D12(84.449,-207.796) D13(83.324,-206.796) D14(84.449,-205.796) D15(83.324,-204.796) D16(84.449,-203.796) D17(83.324,-202.796) D18(84.449,-201.796) D19(83.324,-200.796) D20(84.449,-199.796) D21(83.324,-198.796) D22(84.449,-197.796) D23(83.324,-196.796) D24(84.449,-195.796) D25(83.324,-194.796) D26(84.449,-193.796) D27(83.324,-192.796) D28(84.449,-191.796) D29(83.324,-190.796) D30(84.449,-189.796) D31(83.324,-188.796) D32(84.449,-187.796) D33(83.324,-186.796) D34(84.449,-185.796) D35(83.324,-184.796) D36(84.449,-183.796) D37(83.324,-182.796) D38(84.449,-181.796) D39(83.324,-180.796) D40(84.449,-179.796) D41(83.324,-178.796) D42(84.449,-177.796) D43(83.324,-176.796) D44(84.449,-175.796) D45(83.324,-174.796) D46(84.449,-173.796) D47(83.324,-172.796) D48(84.449,-171.796) D49(83.324,-170.796) D50(84.449,-169.796) D51(83.324,-168.796) D52(84.449,-167.796) D53(83.324,-166.796) D54(84.449,-165.796) D55(83.324,-164.796) D56(84.449,-163.796) D57(83.324,-162.796) D58(84.449,-161.796) D59(83.324,-160.796) D60(84.449,-159.796) D61(83.324,-158.796) E5(81.075,-214.796) E6(82.199,-213.796) E7(81.075,-212.796) E8(82.199,-211.796) E9(81.075,-210.796) E10(82.199,-209.796) E11(81.075,-208.796) E12(82.199,-207.796) E13(81.075,-206.796) E14(82.199,-205.796) E15(81.075,-204.796) E16(82.199,-203.796) E17(81.075,-202.796) E18(82.199,-201.796) E19(81.075,-200.796) E20(82.199,-199.796) E21(81.075,-198.796) E22(82.199,-197.796) E23(81.075,-196.796) E24(82.199,-195.796) E25(81.075,-194.796) E26(82.199,-193.796) E27(81.075,-192.796) E28(82.199,-191.796) E29(81.075,-190.796) E30(82.199,-189.796) E31(81.075,-188.796) E32(82.199,-187.796) E33(81.075,-186.796) E34(82.199,-185.796) E35(81.075,-184.796) E36(82.199,-183.796) E37(81.075,-182.796) E38(82.199,-181.796) E39(81.075,-180.796) E40(82.199,-179.796) E41(81.075,-178.796) E42(82.199,-177.796) E43(81.075,-176.796) E44(82.199,-175.796) E45(81.075,-174.796) E46(82.199,-173.796) E47(81.075,-172.796) E48(82.199,-171.796) E49(81.075,-170.796) E50(82.199,-169.796) E51(81.075,-168.796) E52(82.199,-167.796) E53(81.075,-166.796) E54(82.199,-165.796) E55(81.075,-164.796) E56(82.199,-163.796) E57(81.075,-162.796) E58(82.199,-161.796) E59(81.075,-160.796) E60(82.199,-159.796) E61(81.075,-158.796) F5(78.825,-214.796) F6(79.95,-213.796) F7(78.825,-212.796) F8(79.95,-211.796) F9(78.825,-210.796) F10(79.95,-209.796) F11(78.825,-208.796) F12(79.95,-207.796) F13(78.825,-206.796) F14(79.95,-205.796) F15(78.825,-204.796) F16(79.95,-203.796) F17(78.825,-202.796) F18(79.95,-201.796) F19(78.825,-200.796) F20(79.95,-199.796) F21(78.825,-198.796) F22(79.95,-197.796) F23(78.825,-196.796) F24(79.95,-195.796) F25(78.825,-194.796) F26(79.95,-193.796) F27(78.825,-192.796) F28(79.95,-191.796) F29(78.825,-190.796) F30(79.95,-189.796) F31(78.825,-188.796) F32(79.95,-187.796) F33(78.825,-186.796) F34(79.95,-185.796) F35(78.825,-184.796) F36(79.95,-183.796) F37(78.825,-182.796) F38(79.95,-181.796) F39(78.825,-180.796) F40(79.95,-179.796) F41(78.825,-178.796) F42(79.95,-177.796) F43(78.825,-176.796) F44(79.95,-175.796) F45(78.825,-174.796) F46(79.95,-173.796) F47(78.825,-172.796) F48(79.95,-171.796) F49(78.825,-170.796) F50(79.95,-169.796) F51(78.825,-168.796) F52(79.95,-167.796) F53(78.825,-166.796) F54(79.95,-165.796) F55(78.825,-164.796) F56(79.95,-163.796) F57(78.825,-162.796) F58(79.95,-161.796) F59(78.825,-160.796) F60(79.95,-159.796) F61(78.825,-158.796) Z5(92.324,-214.796) Z7(92.324,-212.796) Z9(92.324,-210.796) Z11(92.324,-208.796) Z13(92.324,-206.796) Z15(92.324,-204.796) Z17(92.324,-202.796) Z19(92.324,-200.796) Z21(92.324,-198.796) Z23(92.324,-196.796) Z25(92.324,-194.796) Z27(92.324,-192.796) Z29(92.324,-190.796) Z31(92.324,-188.796) Z33(92.324,-186.796) Z35(92.324,-184.796) Z37(92.324,-182.796) Z39(92.324,-180.796) Z41(92.324,-178.796) Z43(92.324,-176.796) Z45(92.324,-174.796) Z47(92.324,-172.796) Z49(92.324,-170.796) Z51(92.324,-168.796) Z53(92.324,-166.796) Z55(92.324,-164.796) Z57(92.324,-162.796) Z59(92.324,-160.796) Z61(92.324,-158.796)
PG_LTXDX_F_X1_PG400ND_SL18_V3
  round 0.051 hole 2.489x2.21 unplated: (108.575,-220.342)
  round 0.508 hole 3.2 unplated: (109.575,-154.842)
  rect 1.016x1.016 smd: A1(114.204,-218.796)
  round 1.016 smd: A2(115.329,-217.796) A3(114.204,-216.796) A4(115.329,-215.796) B1(111.955,-218.796) B2(113.08,-217.796) B3(111.955,-216.796) B4(113.08,-215.796) B62(113.08,-157.796) C1(109.704,-218.796) C2(110.83,-217.796) C3(109.704,-216.796) C4(110.83,-215.796) C62(110.83,-157.796) D1(107.454,-218.796) D2(108.579,-217.796) D3(107.454,-216.796) D4(108.579,-215.796) E1(105.205,-218.796) E2(106.329,-217.796) E3(105.205,-216.796) E4(106.329,-215.796) E62(106.329,-157.796) F1(102.955,-218.796) F2(104.08,-217.796) F3(102.955,-216.796) F4(104.08,-215.796) F62(104.08,-157.796) G2(101.83,-217.796) G4(101.83,-215.796) G6(101.83,-213.796) G8(101.83,-211.796) G10(101.83,-209.796) G12(101.83,-207.796) G14(101.83,-205.796) G16(101.83,-203.796) G18(101.83,-201.796) G20(101.83,-199.796) G22(101.83,-197.796) G24(101.83,-195.796) G26(101.83,-193.796) G28(101.83,-191.796) G30(101.83,-189.796) G32(101.83,-187.796) G34(101.83,-185.796) G36(101.83,-183.796) G38(101.83,-181.796) G40(101.83,-179.796) G42(101.83,-177.796) G44(101.83,-175.796) G46(101.83,-173.796) G48(101.83,-171.796) G50(101.83,-169.796) G52(101.83,-167.796) G54(101.83,-165.796) G56(101.83,-163.796) G58(101.83,-161.796) G60(101.83,-159.796)
  custom 0.257x0.257 smd: A5(114.204,-214.796) A6(115.329,-213.796) A7(114.204,-212.796) A8(115.329,-211.796) A9(114.204,-210.796) A10(115.329,-209.796) A11(114.204,-208.796) A12(115.329,-207.796) A13(114.204,-206.796) A14(115.329,-205.796) A15(114.204,-204.796) A16(115.329,-203.796) A17(114.204,-202.796) A18(115.329,-201.796) A19(114.204,-200.796) A20(115.329,-199.796) A21(114.204,-198.796) A22(115.329,-197.796) A23(114.204,-196.796) A24(115.329,-195.796) A25(114.204,-194.796) A26(115.329,-193.796) A27(114.204,-192.796) A28(115.329,-191.796) A29(114.204,-190.796) A30(115.329,-189.796) A31(114.204,-188.796) A32(115.329,-187.796) A33(114.204,-186.796) A34(115.329,-185.796) A35(114.204,-184.796) A36(115.329,-183.796) A37(114.204,-182.796) A38(115.329,-181.796) A39(114.204,-180.796) A40(115.329,-179.796) A41(114.204,-178.796) A42(115.329,-177.796) A43(114.204,-176.796) A44(115.329,-175.796) A45(114.204,-174.796) A46(115.329,-173.796) A47(114.204,-172.796) A48(115.329,-171.796) A49(114.204,-170.796) A50(115.329,-169.796) A51(114.204,-168.796) A52(115.329,-167.796) A53(114.204,-166.796) A54(115.329,-165.796) A55(114.204,-164.796) A56(115.329,-163.796) A57(114.204,-162.796) A58(115.329,-161.796) A59(114.204,-160.796) A60(115.329,-159.796) A61(114.204,-158.796) B5(111.955,-214.796) B6(113.08,-213.796) B7(111.955,-212.796) B8(113.08,-211.796) B9(111.955,-210.796) B10(113.08,-209.796) B11(111.955,-208.796) B12(113.08,-207.796) B13(111.955,-206.796) B14(113.08,-205.796) B15(111.955,-204.796) B16(113.08,-203.796) B17(111.955,-202.796) B18(113.08,-201.796) B19(111.955,-200.796) B20(113.08,-199.796) B21(111.955,-198.796) B22(113.08,-197.796) B23(111.955,-196.796) B24(113.08,-195.796) B25(111.955,-194.796) B26(113.08,-193.796) B27(111.955,-192.796) B28(113.08,-191.796) B29(111.955,-190.796) B30(113.08,-189.796) B31(111.955,-188.796) B32(113.08,-187.796) B33(111.955,-186.796) B34(113.08,-185.796) B35(111.955,-184.796) B36(113.08,-183.796) B37(111.955,-182.796) B38(113.08,-181.796) B39(111.955,-180.796) B40(113.08,-179.796) B41(111.955,-178.796) B42(113.08,-177.796) B43(111.955,-176.796) B44(113.08,-175.796) B45(111.955,-174.796) B46(113.08,-173.796) B47(111.955,-172.796) B48(113.08,-171.796) B49(111.955,-170.796) B50(113.08,-169.796) B51(111.955,-168.796) B52(113.08,-167.796) B53(111.955,-166.796) B54(113.08,-165.796) B55(111.955,-164.796) B56(113.08,-163.796) B57(111.955,-162.796) B58(113.08,-161.796) B59(111.955,-160.796) B60(113.08,-159.796) B61(111.955,-158.796) C5(109.704,-214.796) C6(110.83,-213.796) C7(109.704,-212.796) C8(110.83,-211.796) C9(109.704,-210.796) C10(110.83,-209.796) C11(109.704,-208.796) C12(110.83,-207.796) C13(109.704,-206.796) C14(110.83,-205.796) C15(109.704,-204.796) C16(110.83,-203.796) C17(109.704,-202.796) C18(110.83,-201.796) C19(109.704,-200.796) C20(110.83,-199.796) C21(109.704,-198.796) C22(110.83,-197.796) C23(109.704,-196.796) C24(110.83,-195.796) C25(109.704,-194.796) C26(110.83,-193.796) C27(109.704,-192.796) C28(110.83,-191.796) C29(109.704,-190.796) C30(110.83,-189.796) C31(109.704,-188.796) C32(110.83,-187.796) C33(109.704,-186.796) C34(110.83,-185.796) C35(109.704,-184.796) C36(110.83,-183.796) C37(109.704,-182.796) C38(110.83,-181.796) C39(109.704,-180.796) C40(110.83,-179.796) C41(109.704,-178.796) C42(110.83,-177.796) C43(109.704,-176.796) C44(110.83,-175.796) C45(109.704,-174.796) C46(110.83,-173.796) C47(109.704,-172.796) C48(110.83,-171.796) C49(109.704,-170.796) C50(110.83,-169.796) C51(109.704,-168.796) C52(110.83,-167.796) C53(109.704,-166.796) C54(110.83,-165.796) C55(109.704,-164.796) C56(110.83,-163.796) C57(109.704,-162.796) C58(110.83,-161.796) C59(109.704,-160.796) C60(110.83,-159.796) C61(109.704,-158.796) D5(107.454,-214.796) D6(108.579,-213.796) D7(107.454,-212.796) D8(108.579,-211.796) D9(107.454,-210.796) D10(108.579,-209.796) D11(107.454,-208.796) D12(108.579,-207.796) D13(107.454,-206.796) D14(108.579,-205.796) D15(107.454,-204.796) D16(108.579,-203.796) D17(107.454,-202.796) D18(108.579,-201.796) D19(107.454,-200.796) D20(108.579,-199.796) D21(107.454,-198.796) D22(108.579,-197.796) D23(107.454,-196.796) D24(108.579,-195.796) D25(107.454,-194.796) D26(108.579,-193.796) D27(107.454,-192.796) D28(108.579,-191.796) D29(107.454,-190.796) D30(108.579,-189.796) D31(107.454,-188.796) D32(108.579,-187.796) D33(107.454,-186.796) D34(108.579,-185.796) D35(107.454,-184.796) D36(108.579,-183.796) D37(107.454,-182.796) D38(108.579,-181.796) D39(107.454,-180.796) D40(108.579,-179.796) D41(107.454,-178.796) D42(108.579,-177.796) D43(107.454,-176.796) D44(108.579,-175.796) D45(107.454,-174.796) D46(108.579,-173.796) D47(107.454,-172.796) D48(108.579,-171.796) D49(107.454,-170.796) D50(108.579,-169.796) D51(107.454,-168.796) D52(108.579,-167.796) D53(107.454,-166.796) D54(108.579,-165.796) D55(107.454,-164.796) D56(108.579,-163.796) D57(107.454,-162.796) D58(108.579,-161.796) D59(107.454,-160.796) D60(108.579,-159.796) D61(107.454,-158.796) E5(105.205,-214.796) E6(106.329,-213.796) E7(105.205,-212.796) E8(106.329,-211.796) E9(105.205,-210.796) E10(106.329,-209.796) E11(105.205,-208.796) E12(106.329,-207.796) E13(105.205,-206.796) E14(106.329,-205.796) E15(105.205,-204.796) E16(106.329,-203.796) E17(105.205,-202.796) E18(106.329,-201.796) E19(105.205,-200.796) E20(106.329,-199.796) E21(105.205,-198.796) E22(106.329,-197.796) E23(105.205,-196.796) E24(106.329,-195.796) E25(105.205,-194.796) E26(106.329,-193.796) E27(105.205,-192.796) E28(106.329,-191.796) E29(105.205,-190.796) E30(106.329,-189.796) E31(105.205,-188.796) E32(106.329,-187.796) E33(105.205,-186.796) E34(106.329,-185.796) E35(105.205,-184.796) E36(106.329,-183.796) E37(105.205,-182.796) E38(106.329,-181.796) E39(105.205,-180.796) E40(106.329,-179.796) E41(105.205,-178.796) E42(106.329,-177.796) E43(105.205,-176.796) E44(106.329,-175.796) E45(105.205,-174.796) E46(106.329,-173.796) E47(105.205,-172.796) E48(106.329,-171.796) E49(105.205,-170.796) E50(106.329,-169.796) E51(105.205,-168.796) E52(106.329,-167.796) E53(105.205,-166.796) E54(106.329,-165.796) E55(105.205,-164.796) E56(106.329,-163.796) E57(105.205,-162.796) E58(106.329,-161.796) E59(105.205,-160.796) E60(106.329,-159.796) E61(105.205,-158.796) F5(102.955,-214.796) F6(104.08,-213.796) F7(102.955,-212.796) F8(104.08,-211.796) F9(102.955,-210.796) F10(104.08,-209.796) F11(102.955,-208.796) F12(104.08,-207.796) F13(102.955,-206.796) F14(104.08,-205.796) F15(102.955,-204.796) F16(104.08,-203.796) F17(102.955,-202.796) F18(104.08,-201.796) F19(102.955,-200.796) F20(104.08,-199.796) F21(102.955,-198.796) F22(104.08,-197.796) F23(102.955,-196.796) F24(104.08,-195.796) F25(102.955,-194.796) F26(104.08,-193.796) F27(102.955,-192.796) F28(104.08,-191.796) F29(102.955,-190.796) F30(104.08,-189.796) F31(102.955,-188.796) F32(104.08,-187.796) F33(102.955,-186.796) F34(104.08,-185.796) F35(102.955,-184.796) F36(104.08,-183.796) F37(102.955,-182.796) F38(104.08,-181.796) F39(102.955,-180.796) F40(104.08,-179.796) F41(102.955,-178.796) F42(104.08,-177.796) F43(102.955,-176.796) F44(104.08,-175.796) F45(102.955,-174.796) F46(104.08,-173.796) F47(102.955,-172.796) F48(104.08,-171.796) F49(102.955,-170.796) F50(104.08,-169.796) F51(102.955,-168.796) F52(104.08,-167.796) F53(102.955,-166.796) F54(104.08,-165.796) F55(102.955,-164.796) F56(104.08,-163.796) F57(102.955,-162.796) F58(104.08,-161.796) F59(102.955,-160.796) F60(104.08,-159.796) F61(102.955,-158.796) Z5(116.454,-214.796) Z7(116.454,-212.796) Z9(116.454,-210.796) Z11(116.454,-208.796) Z13(116.454,-206.796) Z15(116.454,-204.796) Z17(116.454,-202.796) Z19(116.454,-200.796) Z21(116.454,-198.796) Z23(116.454,-196.796) Z25(116.454,-194.796) Z27(116.454,-192.796) Z29(116.454,-190.796) Z31(116.454,-188.796) Z33(116.454,-186.796) Z35(116.454,-184.796) Z37(116.454,-182.796) Z39(116.454,-180.796) Z41(116.454,-178.796) Z43(116.454,-176.796) Z45(116.454,-174.796) Z47(116.454,-172.796) Z49(116.454,-170.796) Z51(116.454,-168.796) Z53(116.454,-166.796) Z55(116.454,-164.796) Z57(116.454,-162.796) Z59(116.454,-160.796) Z61(116.454,-158.796)
PG_LTXDX_F_X1_PMVIX_SL06
  round 0.051 hole 2.489x2.21 unplated: (-36.205,-220.292)
  round 0.508 hole 3.2 unplated: (-35.206,-154.842)
  rect 1.016x1.016 hole 0.559: A1(-30.576,-218.796)
  round 1.016 hole 0.559: A2(-29.451,-217.796) A3(-30.576,-216.796) A4(-29.451,-215.796) A5(-30.576,-214.796) A6(-29.451,-213.796) A7(-30.576,-212.796) A8(-29.451,-211.796) A9(-30.576,-210.796) A10(-29.451,-209.796) A11(-30.576,-208.796) A12(-29.451,-207.796) A13(-30.576,-206.796) A14(-29.451,-205.796) A15(-30.576,-204.796) A16(-29.451,-203.796) A17(-30.576,-202.796) A18(-29.451,-201.796) A19(-30.576,-200.796) A20(-29.451,-199.796) A21(-30.576,-198.796) A22(-29.451,-197.796) A23(-30.576,-196.796) A24(-29.451,-195.796) A25(-30.576,-194.796) A26(-29.451,-193.796) A27(-30.576,-192.796) A28(-29.451,-191.796) A29(-30.576,-190.796) A30(-29.451,-189.796) A31(-30.576,-188.796) A32(-29.451,-187.796) A33(-30.576,-186.796) A34(-29.451,-185.796) A35(-30.576,-184.796) A36(-29.451,-183.796) A37(-30.576,-182.796) A38(-29.451,-181.796) A39(-30.576,-180.796) A40(-29.451,-179.796) A41(-30.576,-178.796) A42(-29.451,-177.796) A43(-30.576,-176.796) A44(-29.451,-175.796) A45(-30.576,-174.796) A46(-29.451,-173.796) A47(-30.576,-172.796) A48(-29.451,-171.796) A49(-30.576,-170.796) A50(-29.451,-169.796) A51(-30.576,-168.796) A52(-29.451,-167.796) A53(-30.576,-166.796) A54(-29.451,-165.796) A55(-30.576,-164.796) A56(-29.451,-163.796) A57(-30.576,-162.796) A58(-29.451,-161.796) A59(-30.576,-160.796) A60(-29.451,-159.796) A61(-30.576,-158.796) B1(-32.825,-218.796) B2(-31.7,-217.796) B3(-32.825,-216.796) B4(-31.7,-215.796) B5(-32.825,-214.796) B6(-31.7,-213.796) B7(-32.825,-212.796) B8(-31.7,-211.796) B9(-32.825,-210.796) B10(-31.7,-209.796) B11(-32.825,-208.796) B12(-31.7,-207.796) B13(-32.825,-206.796) B14(-31.7,-205.796) B15(-32.825,-204.796) B16(-31.7,-203.796) B17(-32.825,-202.796) B18(-31.7,-201.796) B19(-32.825,-200.796) B20(-31.7,-199.796) B21(-32.825,-198.796) B22(-31.7,-197.796) B23(-32.825,-196.796) B24(-31.7,-195.796) B25(-32.825,-194.796) B26(-31.7,-193.796) B27(-32.825,-192.796) B28(-31.7,-191.796) B29(-32.825,-190.796) B30(-31.7,-189.796) B31(-32.825,-188.796) B32(-31.7,-187.796) B33(-32.825,-186.796) B34(-31.7,-185.796) B35(-32.825,-184.796) B36(-31.7,-183.796) B37(-32.825,-182.796) B38(-31.7,-181.796) B39(-32.825,-180.796) B40(-31.7,-179.796) B41(-32.825,-178.796) B42(-31.7,-177.796) B43(-32.825,-176.796) B44(-31.7,-175.796) B45(-32.825,-174.796) B46(-31.7,-173.796) B47(-32.825,-172.796) B48(-31.7,-171.796) B49(-32.825,-170.796) B50(-31.7,-169.796) B51(-32.825,-168.796) B52(-31.7,-167.796) B53(-32.825,-166.796) B54(-31.7,-165.796) B55(-32.825,-164.796) B56(-31.7,-163.796) B57(-32.825,-162.796) B58(-31.7,-161.796) B59(-32.825,-160.796) B60(-31.7,-159.796) B61(-32.825,-158.796) B62(-31.7,-157.796) C1(-35.076,-218.796) C2(-33.95,-217.796) C3(-35.076,-216.796) C4(-33.95,-215.796) C5(-35.076,-214.796) C6(-33.95,-213.796) C7(-35.076,-212.796) C8(-33.95,-211.796) C9(-35.076,-210.796) C10(-33.95,-209.796) C11(-35.076,-208.796) C12(-33.95,-207.796) C13(-35.076,-206.796) C14(-33.95,-205.796) C15(-35.076,-204.796) C16(-33.95,-203.796) C17(-35.076,-202.796) C18(-33.95,-201.796) C19(-35.076,-200.796) C20(-33.95,-199.796) C21(-35.076,-198.796) C22(-33.95,-197.796) C23(-35.076,-196.796) C24(-33.95,-195.796) C25(-35.076,-194.796) C26(-33.95,-193.796) C27(-35.076,-192.796) C28(-33.95,-191.796) C29(-35.076,-190.796) C30(-33.95,-189.796) C31(-35.076,-188.796) C32(-33.95,-187.796) C33(-35.076,-186.796) C34(-33.95,-185.796) C35(-35.076,-184.796) C36(-33.95,-183.796) C37(-35.076,-182.796) C38(-33.95,-181.796) C39(-35.076,-180.796) C40(-33.95,-179.796) C41(-35.076,-178.796) C42(-33.95,-177.796) C43(-35.076,-176.796) C44(-33.95,-175.796) C45(-35.076,-174.796) C46(-33.95,-173.796) C47(-35.076,-172.796) C48(-33.95,-171.796) C49(-35.076,-170.796) C50(-33.95,-169.796) C51(-35.076,-168.796) C52(-33.95,-167.796) C53(-35.076,-166.796) C54(-33.95,-165.796) C55(-35.076,-164.796) C56(-33.95,-163.796) C57(-35.076,-162.796) C58(-33.95,-161.796) C59(-35.076,-160.796) C60(-33.95,-159.796) C61(-35.076,-158.796) C62(-33.95,-157.796) D1(-37.326,-218.796) D2(-36.201,-217.796) D3(-37.326,-216.796) D4(-36.201,-215.796) D5(-37.326,-214.796) D6(-36.201,-213.796) D7(-37.326,-212.796) D8(-36.201,-211.796) D9(-37.326,-210.796) D10(-36.201,-209.796) D11(-37.326,-208.796) D12(-36.201,-207.796) D13(-37.326,-206.796) D14(-36.201,-205.796) D15(-37.326,-204.796) D16(-36.201,-203.796) D17(-37.326,-202.796) D18(-36.201,-201.796) D19(-37.326,-200.796) D20(-36.201,-199.796) D21(-37.326,-198.796) D22(-36.201,-197.796) D23(-37.326,-196.796) D24(-36.201,-195.796) D25(-37.326,-194.796) D26(-36.201,-193.796) D27(-37.326,-192.796) D28(-36.201,-191.796) D29(-37.326,-190.796) D30(-36.201,-189.796) D31(-37.326,-188.796) D32(-36.201,-187.796) D33(-37.326,-186.796) D34(-36.201,-185.796) D35(-37.326,-184.796) D36(-36.201,-183.796) D37(-37.326,-182.796) D38(-36.201,-181.796) D39(-37.326,-180.796) D40(-36.201,-179.796) D41(-37.326,-178.796) D42(-36.201,-177.796) D43(-37.326,-176.796) D44(-36.201,-175.796) D45(-37.326,-174.796) D46(-36.201,-173.796) D47(-37.326,-172.796) D48(-36.201,-171.796) D49(-37.326,-170.796) D50(-36.201,-169.796) D51(-37.326,-168.796) D52(-36.201,-167.796) D53(-37.326,-166.796) D54(-36.201,-165.796) D55(-37.326,-164.796) D56(-36.201,-163.796) D57(-37.326,-162.796) D58(-36.201,-161.796) D59(-37.326,-160.796) D60(-36.201,-159.796) D61(-37.326,-158.796) E1(-39.575,-218.796) E2(-38.451,-217.796) E3(-39.575,-216.796) E4(-38.451,-215.796) E5(-39.575,-214.796) E6(-38.451,-213.796) E7(-39.575,-212.796) E8(-38.451,-211.796) E9(-39.575,-210.796) E10(-38.451,-209.796) E11(-39.575,-208.796) E12(-38.451,-207.796) E13(-39.575,-206.796) E14(-38.451,-205.796) E15(-39.575,-204.796) E16(-38.451,-203.796) E17(-39.575,-202.796) E18(-38.451,-201.796) E19(-39.575,-200.796) E20(-38.451,-199.796) E21(-39.575,-198.796) E22(-38.451,-197.796) E23(-39.575,-196.796) E24(-38.451,-195.796) E25(-39.575,-194.796) E26(-38.451,-193.796) E27(-39.575,-192.796) E28(-38.451,-191.796) E29(-39.575,-190.796) E30(-38.451,-189.796) E31(-39.575,-188.796) E32(-38.451,-187.796) E33(-39.575,-186.796) E34(-38.451,-185.796) E35(-39.575,-184.796) E36(-38.451,-183.796) E37(-39.575,-182.796) E38(-38.451,-181.796) E39(-39.575,-180.796) E40(-38.451,-179.796) E41(-39.575,-178.796) E42(-38.451,-177.796) E43(-39.575,-176.796) E44(-38.451,-175.796) E45(-39.575,-174.796) E46(-38.451,-173.796) E47(-39.575,-172.796) E48(-38.451,-171.796) E49(-39.575,-170.796) E50(-38.451,-169.796) E51(-39.575,-168.796) E52(-38.451,-167.796) E53(-39.575,-166.796) E54(-38.451,-165.796) E55(-39.575,-164.796) E56(-38.451,-163.796) E57(-39.575,-162.796) E58(-38.451,-161.796) E59(-39.575,-160.796) E60(-38.451,-159.796) E61(-39.575,-158.796) E62(-38.451,-157.796) F1(-41.825,-218.796) F2(-40.7,-217.796) F3(-41.825,-216.796) F4(-40.7,-215.796) F5(-41.825,-214.796) F6(-40.7,-213.796) F7(-41.825,-212.796) F8(-40.7,-211.796) F9(-41.825,-210.796) F10(-40.7,-209.796) F11(-41.825,-208.796) F12(-40.7,-207.796) F13(-41.825,-206.796) F14(-40.7,-205.796) F15(-41.825,-204.796) F16(-40.7,-203.796) F17(-41.825,-202.796) F18(-40.7,-201.796) F19(-41.825,-200.796) F20(-40.7,-199.796) F21(-41.825,-198.796) F22(-40.7,-197.796) F23(-41.825,-196.796) F24(-40.7,-195.796) F25(-41.825,-194.796) F26(-40.7,-193.796) F27(-41.825,-192.796) F28(-40.7,-191.796) F29(-41.825,-190.796) F30(-40.7,-189.796) F31(-41.825,-188.796) F32(-40.7,-187.796) F33(-41.825,-186.796) F34(-40.7,-185.796) F35(-41.825,-184.796) F36(-40.7,-183.796) F37(-41.825,-182.796) F38(-40.7,-181.796) F39(-41.825,-180.796) F40(-40.7,-179.796) F41(-41.825,-178.796) F42(-40.7,-177.796) F43(-41.825,-176.796) F44(-40.7,-175.796) F45(-41.825,-174.796) F46(-40.7,-173.796) F47(-41.825,-172.796) F48(-40.7,-171.796) F49(-41.825,-170.796) F50(-40.7,-169.796) F51(-41.825,-168.796) F52(-40.7,-167.796) F53(-41.825,-166.796) F54(-40.7,-165.796) F55(-41.825,-164.796) F56(-40.7,-163.796) F57(-41.825,-162.796) F58(-40.7,-161.796) F59(-41.825,-160.796) F60(-40.7,-159.796) F61(-41.825,-158.796) F62(-40.7,-157.796) G2(-42.95,-217.796) G4(-42.95,-215.796) G6(-42.95,-213.796) G8(-42.95,-211.796) G10(-42.95,-209.796) G12(-42.95,-207.796) G14(-42.95,-205.796) G16(-42.95,-203.796) G18(-42.95,-201.796) G20(-42.95,-199.796) G22(-42.95,-197.796) G24(-42.95,-195.796) G26(-42.95,-193.796) G28(-42.95,-191.796) G30(-42.95,-189.796) G32(-42.95,-187.796) G34(-42.95,-185.796) G36(-42.95,-183.796) G38(-42.95,-181.796) G40(-42.95,-179.796) G42(-42.95,-177.796) G44(-42.95,-175.796) G46(-42.95,-173.796) G48(-42.95,-171.796) G50(-42.95,-169.796) G52(-42.95,-167.796) G54(-42.95,-165.796) G56(-42.95,-163.796) G58(-42.95,-161.796) G60(-42.95,-159.796)
  custom 0.257x0.257 smd: Z5(-28.326,-214.796) Z7(-28.326,-212.796) Z9(-28.326,-210.796) Z11(-28.326,-208.796) Z13(-28.326,-206.796) Z15(-28.326,-204.796) Z17(-28.326,-202.796) Z19(-28.326,-200.796) Z21(-28.326,-198.796) Z23(-28.326,-196.796) Z25(-28.326,-194.796) Z27(-28.326,-192.796) Z29(-28.326,-190.796) Z31(-28.326,-188.796) Z33(-28.326,-186.796) Z35(-28.326,-184.796) Z37(-28.326,-182.796) Z39(-28.326,-180.796) Z41(-28.326,-178.796) Z43(-28.326,-176.796) Z45(-28.326,-174.796) Z47(-28.326,-172.796) Z49(-28.326,-170.796) Z51(-28.326,-168.796) Z53(-28.326,-166.796) Z55(-28.326,-164.796) Z57(-28.326,-162.796) Z59(-28.326,-160.796) Z61(-28.326,-158.796)
